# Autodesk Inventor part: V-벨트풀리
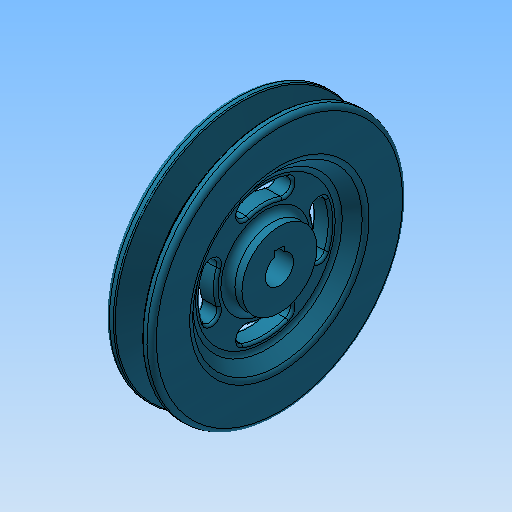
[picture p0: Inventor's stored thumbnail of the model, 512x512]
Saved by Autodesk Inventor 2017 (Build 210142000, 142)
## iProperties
Created: 2015-12
Part Number: V-벨트풀리
Document SubType Name: Modeling
Designer: mdu
Density: 8.08 g/cm^3
Material: 스테인리스강
Mass: 919.289 g
Surface Area: 326.109 cm^2
Volume: 113.773 cm^3
Appearance: 터키옥색
Author: mdu
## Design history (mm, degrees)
sketch "스케치1"
  geometry: L1 (-10, 0)-(10, 0); L2 (-10, 0)-(-10, 16); L3 (-10, 16)-(-4, 16); L4 (-4, 16)-(-4, 31); L5 (-4, 31)-(-10, 37); L6 (-10, 37)-(-10, 54.5); L7 (-10, 54.5)-(-5.976, 54.5); L8 (-5.976, 54.5)-(-2.154, 42); L9 (-2.154, 42)-(2.154, 42); L10 (2.154, 42)-(5.976, 54.5); L11 (5.976, 54.5)-(10, 54.5); L12 (10, 54.5)-(10, 37); L13 (10, 37)-(4, 31); L14 (4, 31)-(4, 16); L15 (4, 16)-(10, 16); L16 (10, 16)-(10, 0); L17 (-4.6, 50)-(4.6, 50); 2 further points
  constraints: 34 end point, 7 parallel, 6 equal length, 5 collinear, 3 perpendicular, 2 point on line, 1 coincident, 1 horizontal, 1 midpoint
  dimensions: "d0" = 20 distance of L1.start L1.end; "d1" = 9.2 distance of L17.start L17.end; "d2" = 34 deg angle of L10 L8; "d3" = 4.5 distance between parallel lines of L7 L17; "d4" = 8 distance between parallel lines of L9 L17; "d6" = 100 diameter of L17 L1; "d7" = 32 diameter of L3 L1; "d8" = 74 diameter of L5.end L1; "d9" = 6 distance of L2.end L3.end; "d10" = 135 deg angle of L4 L5
revolve "회전1" sketch "스케치1" stored, may be unused: angle "d11" = 90 deg
fillet "모깎기1" dims "d12" = 2, "d13" = 0.5, "d14" = 1, "d15" = 3
sketch "스케치2"
  geometry: L1 (-2, 5.657)-(-2, 7.8); L2 (-2, 7.8)-(2, 7.8); L3 (2, 7.8)-(2, 5.657); A1 r 6 centre (0, 0) between (-2, 5.657) and (2, 5.657); 1 further point
  constraints: 6 end point, 2 parallel, 2 point on circle, 1 centre point, 1 coincident, 1 perpendicular, 1 vertical
  dimensions: "d16" = 12 diameter of A1; "d17" = 4 distance of L1.end L2.end; "d18" = 13.8 dimension on A1 L2 (computed from d16)
extrude "돌출1" cut sketch "스케치2" stored distance "d19" = 10; taper "d20" = 0 deg
sketch "스케치3"
  geometry: L1 (0, 0)-(0, 24.5); L2 (0, 0)-(-8.379, 23.022); C1 r 29.757 at (0, 0) reference; C2 r 19 at (0, 0) reference; A1 r 24.5 centre (0, 0) between (0, 24.5) and (-8.379, 23.022); A2 r 3.3 centre (-8.379, 23.022) between (-9.508, 26.123) and (-7.251, 19.921); A3 r 3.3 centre (8.379, 23.022) between (7.251, 19.921) and (9.508, 26.123); A4 r 27.8 centre (0, 0) between (9.508, 26.123) and (-9.508, 26.123); A5 r 21.2 centre (0, 0) between (7.251, 19.921) and (-7.251, 19.921); 1 further point
  constraints: 10 point on circle, 5 centre point, 4 coincident, 4 end point, 1 point on line, 1 symmetric about line, 1 tangent, 1 vertical, 1 other
  dimensions: "d24" = 49 diameter of A1; "d27" = 20 deg angle of L1 L2; "d29" = 6.6 diameter of A2
extrude "돌출2" cut sketch "스케치3" stored distance "d30" = 10; taper "d31" = 0 deg
fillet "모깎기2" dims "d32" = 1
node "솔리드1"
pattern_circular "원형 패턴1" dims angle "d34" = 360 deg
